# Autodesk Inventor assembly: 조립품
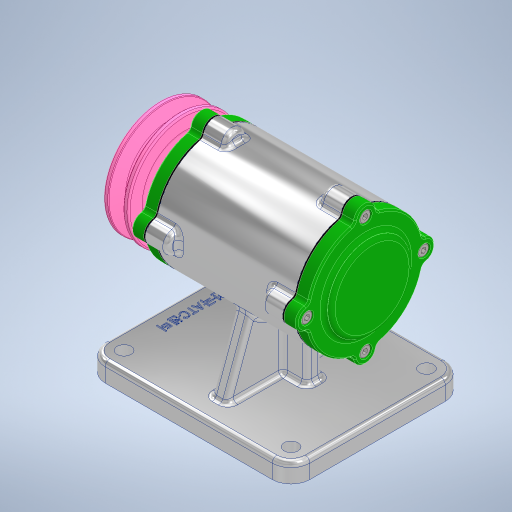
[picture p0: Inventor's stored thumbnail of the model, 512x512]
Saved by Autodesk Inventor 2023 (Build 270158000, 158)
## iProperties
Created: 2023-08
Part Number: 조립품
Document SubType Name: Assembly
Designer: asung
Author: asung
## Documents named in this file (12)
- C:\Users\asung\Desktop\730808V1005\조립품.iam
- C:\Users\asung\Desktop\730808V1005\본체.ipt
- C:\Users\asung\Desktop\730808V1005\앞커버.ipt
- C:\Users\asung\Desktop\730808V1005\뒤커버.ipt
- C:\Users\asung\Desktop\730808V1005\개스킷.ipt
- C:\Users\asung\Desktop\730808V1005\베어링 6204.ipt
- C:\Users\asung\Desktop\730808V1005\축.ipt
- C:\Users\asung\Desktop\730808V1005\오일 실.ipt
- C:\Users\asung\Desktop\730808V1005\키 4 x 4.ipt
- C:\Users\asung\Desktop\730808V1005\볼트 M4 x 12.ipt
- C:\Users\asung\Desktop\730808V1005\V-벨트풀리.ipt
- C:\Users\asung\Desktop\730808V1005\너트 M12 x 1.25.ipt
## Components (8 placed, 6 different names)
1. 개스킷:1
2. 개스킷:2
3. KS B 2023 6204 - 20 x 47 x 14:1
4. KS B 2023 6204 - 20 x 47 x 14:2
5. KS B 2804 D D - 20 32 8:1
6. KS B 1311 (I) 4 x 4 x 12:1
7. V-벨트풀리:1
8. KS B 1012 클래스 1 일반 - 미터 M12x1.25:1
